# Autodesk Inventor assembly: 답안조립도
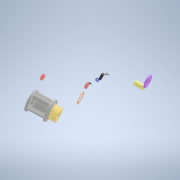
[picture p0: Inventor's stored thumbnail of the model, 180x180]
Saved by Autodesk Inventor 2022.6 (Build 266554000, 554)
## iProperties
Created: 2024-10
Part Number: 답안조립도
Document SubType Name: Assembly
Designer: Class 001
Author: Class 001
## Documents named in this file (18)
- C:\Users\Class 001\Desktop\741004V1011\답안조립도.iam
- C:\Users\Class 001\Desktop\741004V1011\본체.ipt
- C:\Users\Class 001\Desktop\741004V1011\축.ipt
- C:\Users\Class 001\Desktop\741004V1011\평행키 5x5x22.ipt
- C:\Users\Class 001\Desktop\741004V1011\V 벨트 풀리.ipt
- C:\Users\Class 001\Desktop\741004V1011\가스켓.ipt
- C:\Users\Class 001\Desktop\741004V1011\깊은 홈 볼베어링 6004.ipt
- C:\Users\Class 001\Desktop\741004V1011\스러스트 볼베어링 512 02.ipt
- C:\Users\Class 001\Desktop\741004V1011\스프링와셔 M5.ipt
- C:\Users\Class 001\Desktop\741004V1011\실링 패드.ipt
- C:\Users\Class 001\Desktop\741004V1011\어뎁터.ipt
- C:\Users\Class 001\Desktop\741004V1011\엔드캡.ipt
- C:\Users\Class 001\Desktop\741004V1011\오일 실 20 35 8.ipt
- C:\Users\Class 001\Desktop\741004V1011\육각 머리 볼트 M6x0.75x12.ipt
- C:\Users\Class 001\Desktop\741004V1011\육각 소켓 머리 볼트 M5x10.ipt
- C:\Users\Class 001\Desktop\741004V1011\칼라.ipt
- C:\Users\Class 001\Desktop\741004V1011\커버.ipt
- C:\Users\Class 001\Desktop\741004V1011\평와셔 M5.ipt
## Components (2 placed, 2 different names)
1. V 벨트 풀리:1
2. 가스켓:1
